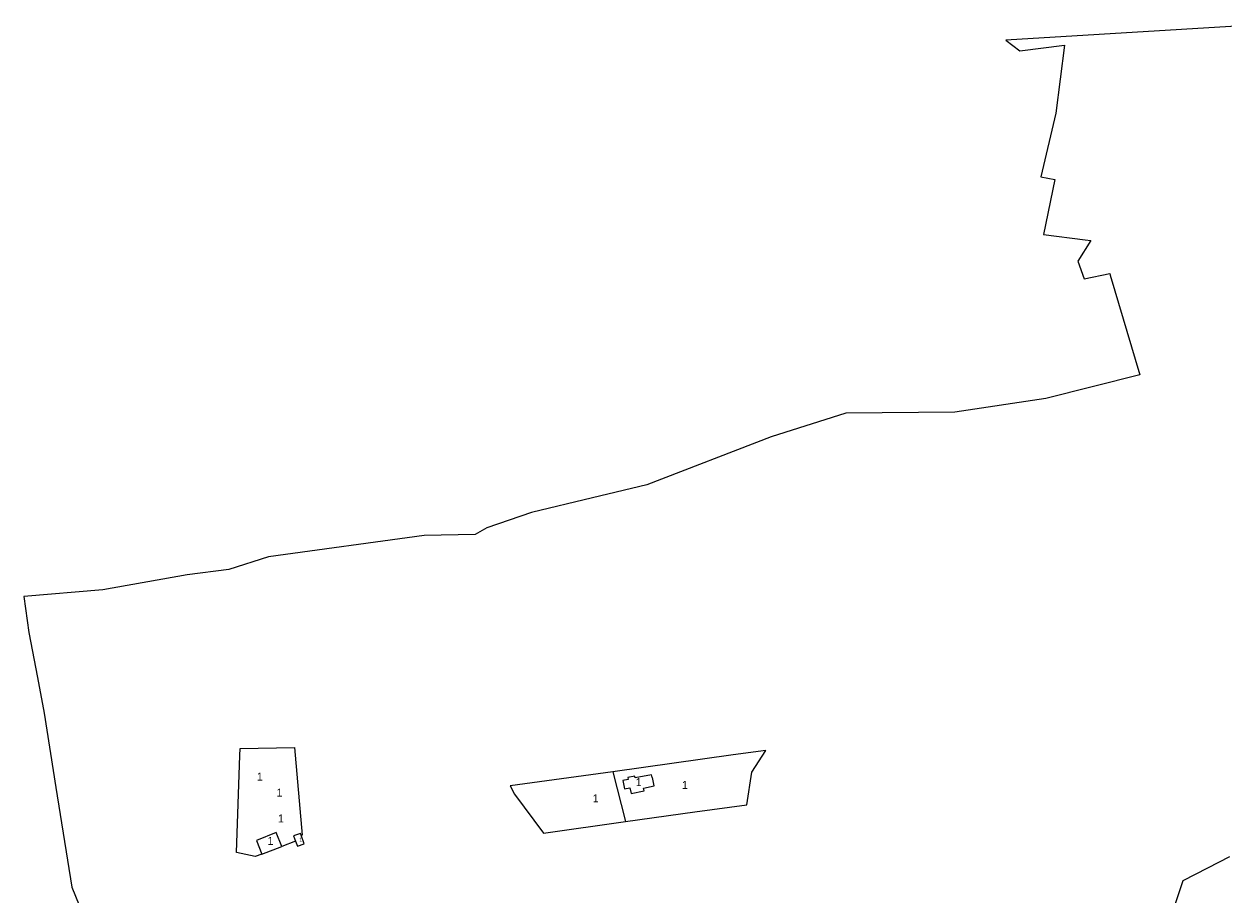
# Model space of a CAD drawing. Extents: x -494856 to -492815, y -1145343 to -1142968.
# Drawn here: x -494617 to -494018, y -1144829 to -1144394 of the extents above; entities that cross this region are included whole.
import ezdxf

# ---------------------------------------------------------------- set-up
doc = ezdxf.new("R2010")
doc.units = 0
for name, color, linetype in [('Level 255', 7, 'Continuous'), ('NERES_SET', 7, 'Continuous'), ('OVNE_SET', 7, 'Continuous')]:
    doc.layers.add(name, color=color, linetype=linetype)

msp = doc.modelspace()

# ---------------------------------------------------------------- linework, layer by layer
at = {"layer": 'NERES_SET'}
msp.add_line((-494322.77, -1144767.71), (-494316.39, -1144792.67), dxfattribs=at)
for points in [[(-494498.05, -1144808.98), (-494501.53, -1144810.07), (-494510.8, -1144808.15), (-494509.12, -1144759.53), (-494509, -1144756.1)], [(-494509, -1144756.1), (-494481.82, -1144755.65), (-494478.05, -1144799.36), (-494478.53, -1144799.47), (-494478.87, -1144798.54), (-494482.31, -1144799.83), (-494481.34, -1144802.4), (-494488.15, -1144805.08), (-494490.91, -1144798.18), (-494500.8, -1144802.07), (-494498.05, -1144808.98), (-494488.15, -1144805.08)], [(-494357.39, -1144798.38), (-494316.39, -1144792.67), (-494281.64, -1144787.83), (-494255.81, -1144784.23), (-494253.2, -1144768), (-494246.29, -1144757.06), (-494262.64, -1144759.33), (-494322.77, -1144767.71), (-494374.01, -1144774.85), (-494371.9, -1144778.89), (-494357.39, -1144798.38)], [(-494311.65, -1144769.95), (-494315.25, -1144770.68), (-494315.07, -1144771.56), (-494317.71, -1144772.12), (-494316.83, -1144776.35), (-494314.21, -1144775.85), (-494313.61, -1144778.68), (-494307.09, -1144777.34), (-494307.4, -1144775.88), (-494302.11, -1144774.8), (-494302.94, -1144770.64), (-494303.09, -1144770.67), (-494303.39, -1144769.2), (-494311.48, -1144770.83), (-494311.65, -1144769.95)], [(-494481.34, -1144802.4), (-494480.38, -1144804.96), (-494476.99, -1144803.69), (-494478.53, -1144799.47)]]:
    msp.add_lwpolyline(points, dxfattribs=at)
at = {"layer": 'OVNE_SET'}
for points in [[(-493991.9, -1144393.92), (-494126.29, -1144401.94), (-494119.37, -1144407.34), (-494097, -1144404.51), (-494101.29, -1144438.45), (-494108.87, -1144470.41), (-494101.75, -1144471.64), (-494107.41, -1144499.1), (-494086.72, -1144501.78), (-494083.86, -1144502.15), (-494090.3, -1144512.45), (-494087.12, -1144521.3), (-494074.39, -1144518.63), (-494074.14, -1144519.48), (-494059.27, -1144569.36), (-494106.25, -1144581.17), (-494151.74, -1144588.03), (-494206.18, -1144588.56), (-494243.59, -1144600.33), (-494305.7, -1144624.24), (-494332.82, -1144630.88), (-494363.43, -1144638.06), (-494385.7, -1144645.83), (-494391.56, -1144649.2), (-494416.94, -1144649.67), (-494494.84, -1144660.23), (-494514.56, -1144666.69), (-494535.49, -1144669.27), (-494577.61, -1144676.85), (-494617.01, -1144680.18), (-494614.54, -1144698.14), (-494610.24, -1144720.63), (-494606.99, -1144738.41), (-494601.06, -1144775.55), (-494593.09, -1144825.51), (-494589.38, -1144834.48)], [(-494054.38, -1144871.96), (-494037.58, -1144822.11), (-494025.28, -1144815.77), (-494014.28, -1144810.1)]]:
    msp.add_lwpolyline(points, dxfattribs=at)

# ---------------------------------------------------------------- texts
at = {"layer": 'Level 255'}
for height, p in [(4, (-494500.62, -1144772.18)), (4, (-494311.26, -1144774.9)), (4, (-494288.13, -1144776.33)), (4, (-494490.81, -1144780.18)), (4, (-494332.77, -1144783.03)), (4, (-494490.07, -1144793.09)), (4, (-494495.29, -1144804.29)), (2, (-494479.46, -1144802.69))]:
    msp.add_text('1', height=height, dxfattribs=at).set_placement(p)

doc.saveas('drawing.dxf')
